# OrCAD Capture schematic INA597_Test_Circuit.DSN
size A; title: INA597 High-Precision, Wide-Bandwidth e-trim™; rev: 1.1; note: Datasheet: SBOS385B  EVM: N/A
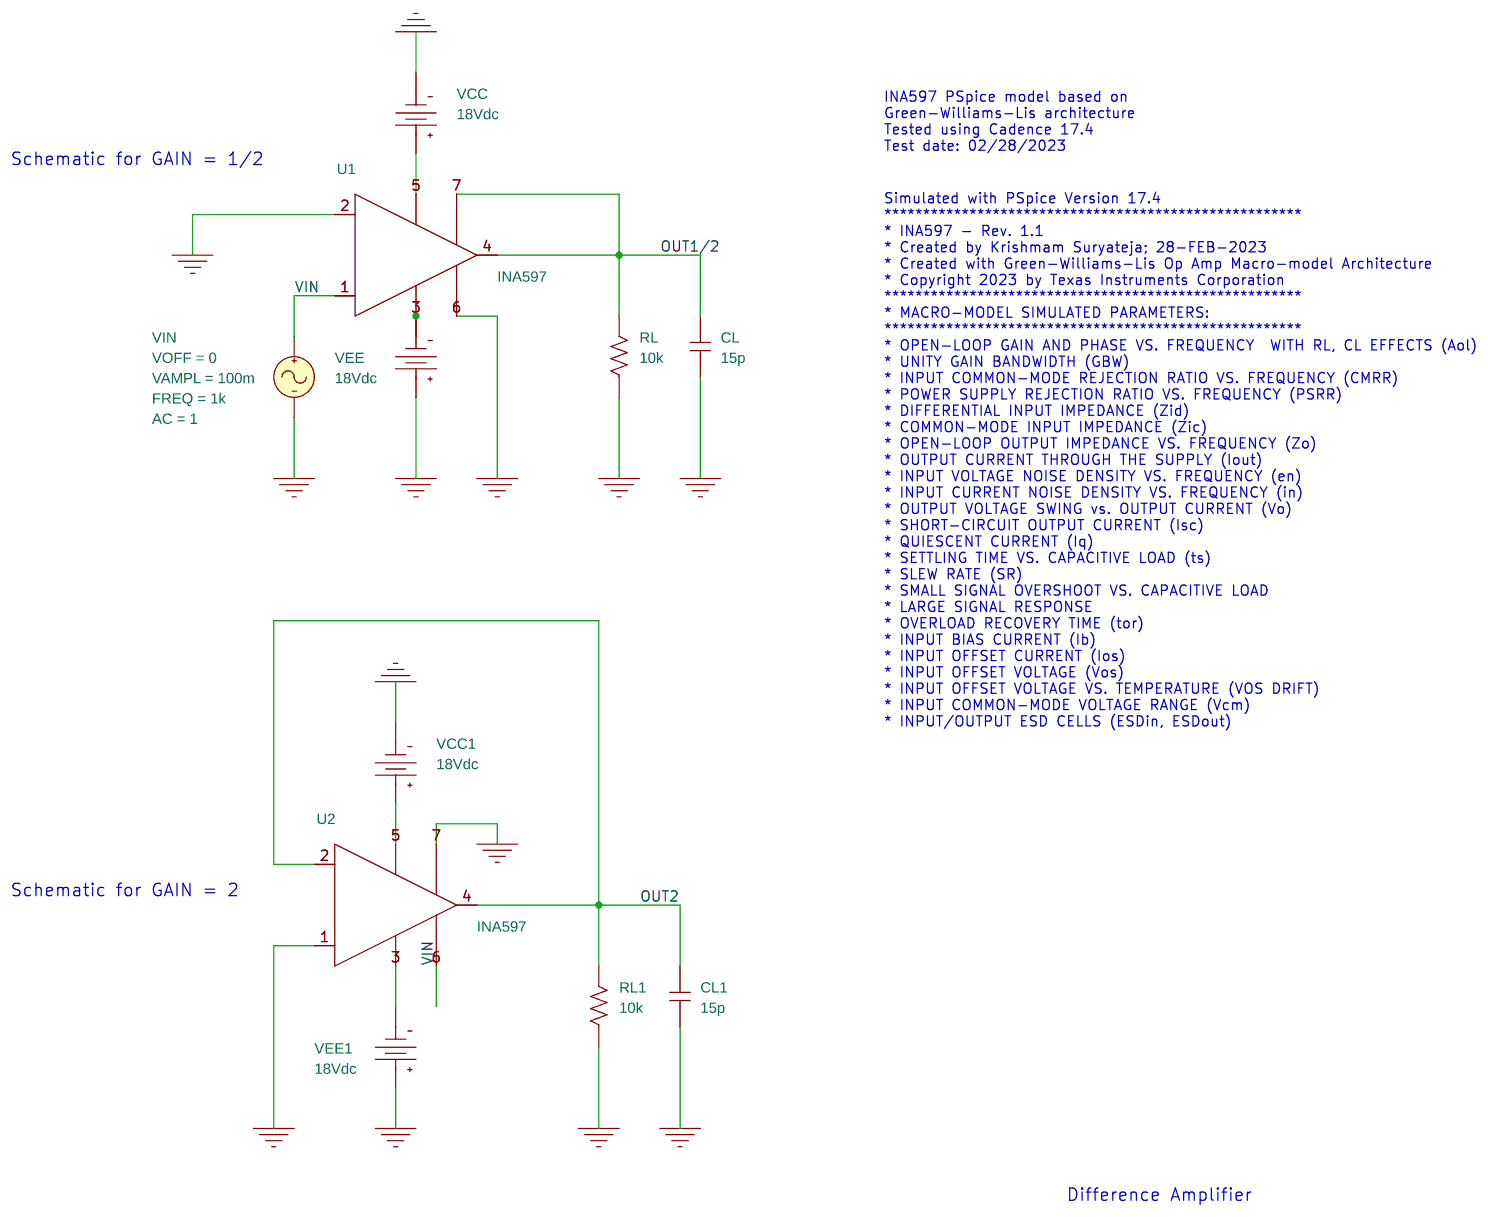
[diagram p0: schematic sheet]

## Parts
CL  15p  [RAD/CK05]
CL1  15p  [RAD/CK05]
RL  10k  [AX/RC05]
RL1  10k  [AX/RC05]
U1  INA597
U2  INA597
VCC  VDC
VCC1  VDC
VEE  VDC
VEE1  VDC
VIN  VSIN

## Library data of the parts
CL CL1 = C
RL RL1 = R
U1 U2 = INA597
VCC VCC1 VEE VEE1 = VDC: DC: 18Vdc
VIN = VSIN: AC: 1; FREQ: 1k; VAMPL: 100m; VOFF: 0

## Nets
VIN: U1.1(+) U2.6(REF) VIN.1(+)
0: CL.1 CL1.1 RL.1 RL1.1 U1.2(-) U1.6(REF) U2.1(+) U2.7(SENSE) VCC.1(-) VCC1.1(-) VEE.0(+) VEE1.0(+) VIN.2(-)
OUT1/2: CL.2 RL.2 U1.4(OUT) U1.7(SENSE)
OUT2: CL1.2 RL1.2 U2.2(-) U2.4(OUT)
N12680: U1.5(V+) VCC.0(+)
N13070: U1.3(V-) VEE.1(-)
N1657141: U2.5(V+) VCC1.0(+)
N1657557: U2.3(V-) VEE1.1(-)

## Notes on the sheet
- INA597 PSpice model based on
  Green-Williams-Lis architecture
  Tested using Cadence 17.4
  Test date: 02/28/2023
- Schematic for GAIN = 1/2
- Simulated with PSpice Version 17.4
  ******************************************************
  * INA597 - Rev. 1.1
  * Created by Krishmam Suryateja; 28-FEB-2023
  * Created with Green-Williams-Lis Op Amp Macro-model Architecture
  * Copyright 2023 by Texas Instruments Corporation
  ******************************************************
  * MACRO-MODEL SIMULATED PARAMETERS:
  ******************************************************
  * OPEN-LOOP GAIN AND PHASE VS. FREQUENCY  WITH RL, CL EFFECTS (Aol)
  * UNITY GAIN BANDWIDTH (GBW)
  * INPUT COMMON-MODE REJECTION RATIO VS. FREQUENCY (CMRR)
  * POWER SUPPLY REJECTION RATIO VS. FREQUENCY (PSRR)
  * DIFFERENTIAL INPUT IMPEDANCE (Zid)
  * COMMON-MODE INPUT IMPEDANCE (Zic)
  * OPEN-LOOP OUTPUT IMPEDANCE VS. FREQUENCY (Zo)
  * OUTPUT CURRENT THROUGH THE SUPPLY (Iout)
  * INPUT VOLTAGE NOISE DENSITY VS. FREQUENCY (en)
  * INPUT CURRENT NOISE DENSITY VS. FREQUENCY (in)
  * OUTPUT VOLTAGE SWING vs. OUTPUT CURRENT (Vo)
  * SHORT-CIRCUIT OUTPUT CURRENT (Isc)
  * QUIESCENT CURRENT (Iq)
  * SETTLING TIME VS. CAPACITIVE LOAD (ts)
  * SLEW RATE (SR)
  * SMALL SIGNAL OVERSHOOT VS. CAPACITIVE LOAD
  * LARGE SIGNAL RESPONSE
  * OVERLOAD RECOVERY TIME (tor)
  * INPUT BIAS CURRENT (Ib)
  * INPUT OFFSET CURRENT (Ios)
  * INPUT OFFSET VOLTAGE (Vos)
  * INPUT OFFSET VOLTAGE VS. TEMPERATURE (VOS DRIFT)
  * INPUT COMMON-MODE VOLTAGE RANGE (Vcm)
  * INPUT/OUTPUT ESD CELLS (ESDin, ESDout)
- Schematic for GAIN = 2
- Difference Amplifier
